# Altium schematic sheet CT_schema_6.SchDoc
size 371 x 245 mm
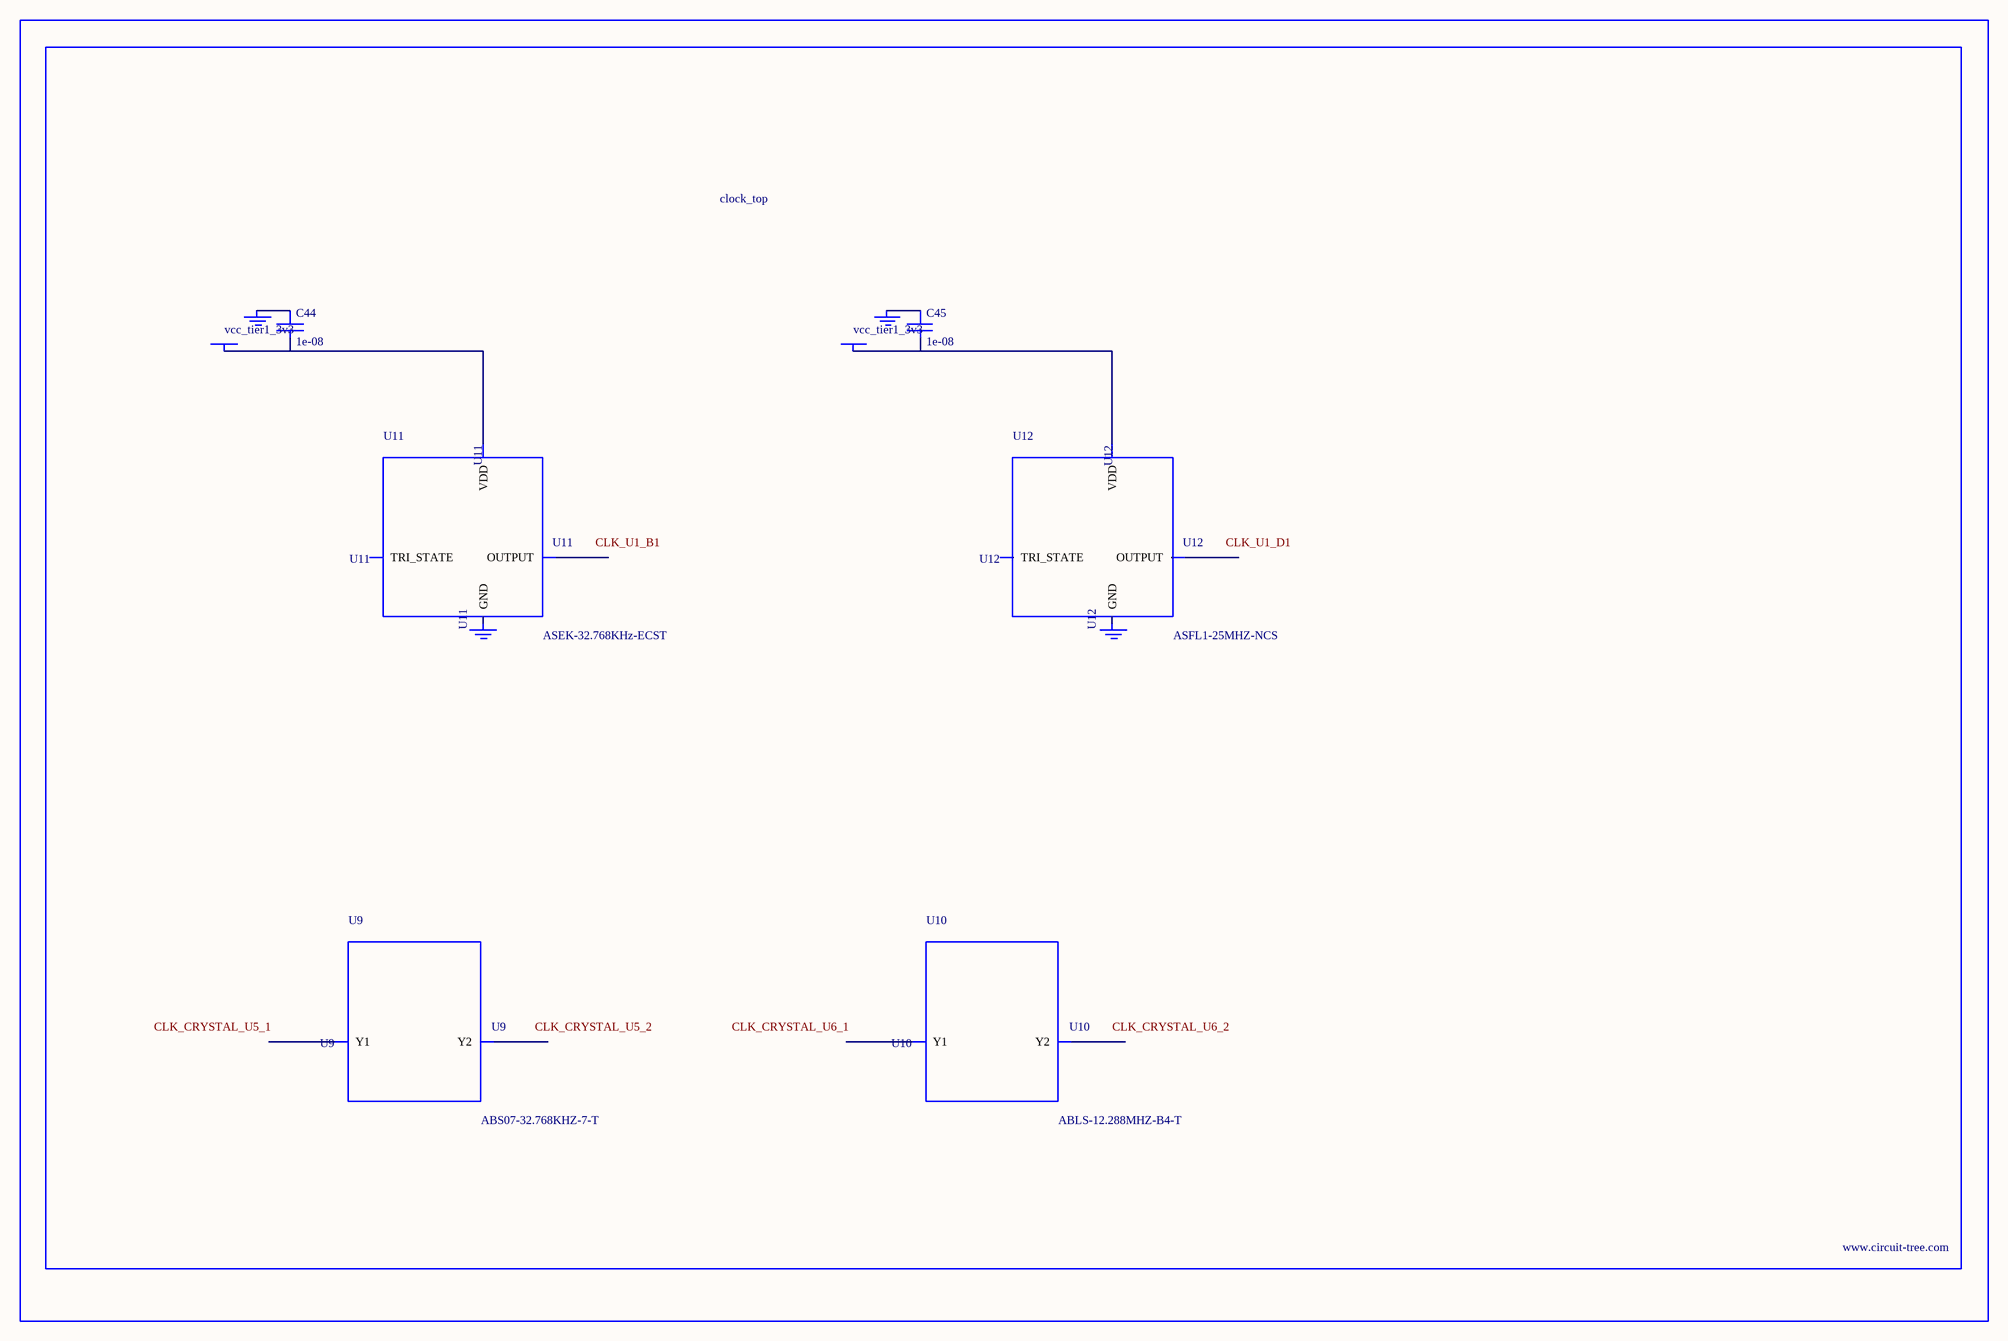
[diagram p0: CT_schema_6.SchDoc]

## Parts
BORDER5  (no value)
C44  1e-08  [C0402]
C45  1e-08  [C0402]
GND_INSTANCE_5_0  (no value)
GND_INSTANCE_5_1  (no value)
GND_INSTANCE_5_2  (no value)
GND_INSTANCE_5_3  (no value)
POWER_INSTANCE_5_0  vcc_tier1_3v3
POWER_INSTANCE_5_1  vcc_tier1_3v3
U9  ABS07-32.768KHZ-7-T  [ABS07-32.768KHZ-7-T]
U10  ABLS-12.288MHZ-B4-T  [ABLS-12.288MHZ-B4-T]
U11  ASEK-32.768KHz-ECST  [ASEK]
U12  ASFL1-25MHZ-NCS  [ASFL1]

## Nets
NetC44_1: C44.1 GND_INSTANCE_5_0.0(GND)
NetC44_2: C44.2 POWER_INSTANCE_5_0.0(PWR) U11.4(VDD)
NetC45_1: C45.1 GND_INSTANCE_5_2.0(GND)
NetC45_2: C45.2 POWER_INSTANCE_5_1.0(PWR) U12.4(VDD)

Not connected (* = marked no-connect by the designer): GND_INSTANCE_5_1 0(GND); GND_INSTANCE_5_3 0(GND); U9 1(Y1) 2(Y2); U10 1(Y1) 2(Y2); U11 1(TRI_STATE) 2(GND) 3(OUTPUT); U12 1(TRI_STATE) 2(GND) 3(OUTPUT)

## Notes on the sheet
- Labels drawn without touching a wire or pin: CLK_CRYSTAL_U5_1, CLK_CRYSTAL_U5_2, CLK_CRYSTAL_U6_1, CLK_CRYSTAL_U6_2, CLK_U1_B1, CLK_U1_D1

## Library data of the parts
BORDER5 = BORDER_PAGE5
C44 C45 = C0402C103K3RAC
GND_INSTANCE_5_0-GND_INSTANCE_5_3 = GND
POWER_INSTANCE_5_0 POWER_INSTANCE_5_1 = PWR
